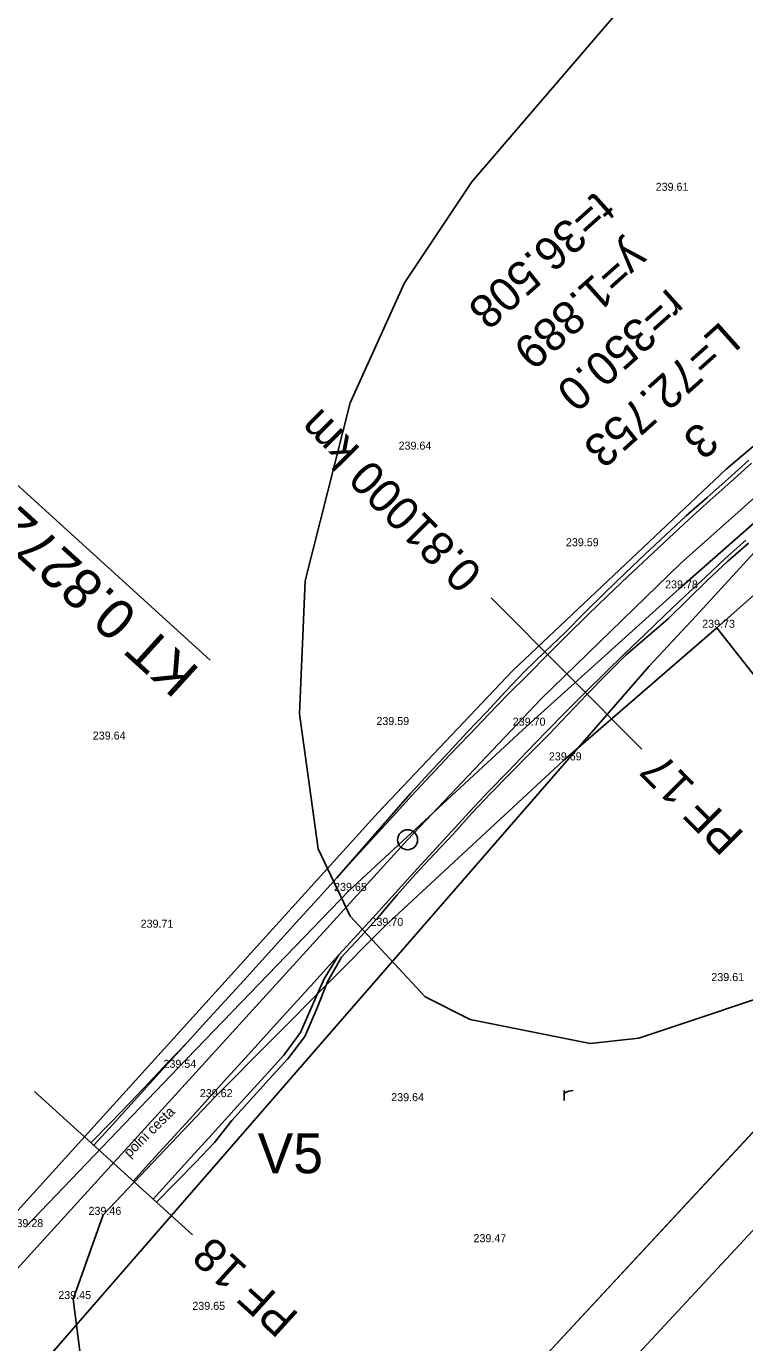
# Model space of a CAD drawing. Extents: x -555887 to -552101, y -1100251 to -1096546.
# Drawn here: x -555426.4 to -555372.6, y -1098751.9 to -1098653.3 of the extents above; entities that cross this region are included whole.
import ezdxf

# ---------------------------------------------------------------- set-up
doc = ezdxf.new("R2010")
doc.units = 0
for name, color, linetype in [('PARCELY_cesty', 7, 'Continuous'), ('POLYGONY_POPIS_CESTY', 7, 'Continuous'), ('POLYGONY_SITUACE_PF', 7, 'Continuous'), ('POLYGONY_SITUACE_PF_POPISY', 7, 'Continuous'), ('POLYGONY_SITUACE_PO', 7, 'Continuous'), ('ram_VC1', 7, 'Continuous'), ('vrstevnice', 7, 'Continuous'), ('Výškopis', 7, 'Continuous'), ('ZSST', 7, 'Continuous'), ('zájem', 7, 'Continuous')]:
    doc.layers.add(name, color=color, linetype=linetype)

msp = doc.modelspace()

# ---------------------------------------------------------------- linework, layer by layer
msp.add_line((-555412.608, -1098700.796), (-555428.216, -1098686.609))
at = {"layer": 'PARCELY_cesty'}
msp.add_lwpolyline([(-555432.8, -1098748.4), (-555400.008, -1098712.208), (-555389.921, -1098701.565), (-555373.936, -1098686.469), (-555357.132, -1098672.276), (-555340.17, -1098659.659), (-555299.833, -1098630.198), (-555259.851, -1098600.294), (-555132.603, -1098503.989), (-555074.98, -1098461.38), (-555070.799, -1098455.669), (-555054.379, -1098443.798), (-555047.89, -1098441.68), (-555024.771, -1098425.173), (-554988.252, -1098399.708), (-554740.35, -1098228.23), (-554737.92, -1098224.21)], dxfattribs=at)
at = {"layer": 'POLYGONY_SITUACE_PF'}
for p, q in [((-555385.902, -1098701.782), (-555391.549, -1098696.116)), ((-555380.254, -1098707.448), (-555385.902, -1098701.782)), ((-555419.844, -1098738.489), (-555425.763, -1098733.108)), ((-555413.924, -1098743.871), (-555419.844, -1098738.489))]:
    msp.add_line(p, q, dxfattribs=at)
at = {"layer": 'POLYGONY_SITUACE_PO'}
for p, q in [((-555366.511, -1098683.861), (-555377.362, -1098693.554)), ((-555372.241, -1098685.8), (-555373.797, -1098687.206)), ((-555372.04, -1098686.028), (-555373.604, -1098687.421)), ((-555372.04, -1098686.028), (-555373.604, -1098687.421)), ((-555373.797, -1098687.206), (-555375.371, -1098688.592)), ((-555373.604, -1098687.421), (-555375.162, -1098688.823)), ((-555373.604, -1098687.421), (-555375.162, -1098688.823)), ((-555375.371, -1098688.592), (-555376.94, -1098689.983)), ((-555375.162, -1098688.823), (-555376.715, -1098690.229)), ((-555375.162, -1098688.823), (-555376.715, -1098690.229)), ((-555376.94, -1098689.983), (-555378.479, -1098691.408)), ((-555376.715, -1098690.229), (-555378.249, -1098691.656)), ((-555376.715, -1098690.229), (-555378.249, -1098691.656)), ((-555378.479, -1098691.408), (-555380.005, -1098692.847)), ((-555378.249, -1098691.656), (-555379.783, -1098693.083)), ((-555378.249, -1098691.656), (-555379.783, -1098693.083)), ((-555372.476, -1098691.787), (-555374.011, -1098693.177)), ((-555372.476, -1098691.787), (-555374.011, -1098693.177)), ((-555372.261, -1098692.025), (-555373.826, -1098693.38)), ((-555380.005, -1098692.847), (-555381.526, -1098694.291)), ((-555379.783, -1098693.083), (-555381.304, -1098694.525)), ((-555379.783, -1098693.083), (-555381.304, -1098694.525)), ((-555374.011, -1098693.177), (-555375.528, -1098694.588)), ((-555374.011, -1098693.177), (-555375.528, -1098694.588)), ((-555377.362, -1098693.554), (-555387.8, -1098703.689)), ((-555373.826, -1098693.38), (-555375.341, -1098694.79)), ((-555381.526, -1098694.291), (-555383.043, -1098695.739)), ((-555381.304, -1098694.525), (-555382.821, -1098695.97)), ((-555381.304, -1098694.525), (-555382.821, -1098695.97)), ((-555375.528, -1098694.588), (-555377.045, -1098695.999)), ((-555375.528, -1098694.588), (-555377.045, -1098695.999)), ((-555375.341, -1098694.79), (-555376.82, -1098696.239)), ((-555383.043, -1098695.739), (-555384.521, -1098697.227)), ((-555382.821, -1098695.97), (-555384.328, -1098697.425)), ((-555382.821, -1098695.97), (-555384.328, -1098697.425)), ((-555377.045, -1098695.999), (-555378.548, -1098697.424)), ((-555377.045, -1098695.999), (-555378.548, -1098697.424)), ((-555376.82, -1098696.239), (-555378.298, -1098697.687)), ((-555384.521, -1098697.227), (-555385.997, -1098698.716)), ((-555384.328, -1098697.425), (-555385.821, -1098698.895)), ((-555384.328, -1098697.425), (-555385.821, -1098698.895)), ((-555378.548, -1098697.424), (-555380.048, -1098698.853)), ((-555378.548, -1098697.424), (-555380.048, -1098698.853)), ((-555378.298, -1098697.687), (-555379.864, -1098699.044)), ((-555385.997, -1098698.716), (-555387.523, -1098700.155)), ((-555385.821, -1098698.895), (-555387.314, -1098700.365)), ((-555385.821, -1098698.895), (-555387.314, -1098700.365)), ((-555380.048, -1098698.853), (-555381.538, -1098700.292)), ((-555380.048, -1098698.853), (-555381.538, -1098700.292)), ((-555379.864, -1098699.044), (-555381.432, -1098700.401)), ((-555387.523, -1098700.155), (-555389.032, -1098701.613)), ((-555387.314, -1098700.365), (-555388.789, -1098701.853)), ((-555387.314, -1098700.365), (-555388.789, -1098701.853)), ((-555381.538, -1098700.292), (-555383.014, -1098701.745)), ((-555381.538, -1098700.292), (-555383.014, -1098701.745)), ((-555381.432, -1098700.401), (-555382.905, -1098701.856)), ((-555389.032, -1098701.613), (-555390.476, -1098703.133)), ((-555388.789, -1098701.853), (-555390.264, -1098703.342)), ((-555388.789, -1098701.853), (-555390.264, -1098703.342)), ((-555383.014, -1098701.745), (-555384.49, -1098703.199)), ((-555383.014, -1098701.745), (-555384.49, -1098703.199)), ((-555382.905, -1098701.856), (-555384.357, -1098703.331)), ((-555387.8, -1098703.689), (-555397.809, -1098714.249)), ((-555390.476, -1098703.133), (-555391.895, -1098704.679)), ((-555390.264, -1098703.342), (-555391.724, -1098704.844)), ((-555390.264, -1098703.342), (-555391.724, -1098704.844)), ((-555384.49, -1098703.199), (-555385.948, -1098704.67)), ((-555384.49, -1098703.199), (-555385.948, -1098704.67)), ((-555384.357, -1098703.331), (-555385.784, -1098704.832)), ((-555391.895, -1098704.679), (-555393.344, -1098706.194)), ((-555391.724, -1098704.844), (-555393.174, -1098706.356)), ((-555391.724, -1098704.844), (-555393.174, -1098706.356)), ((-555385.948, -1098704.67), (-555387.406, -1098706.141)), ((-555385.948, -1098704.67), (-555387.406, -1098706.141)), ((-555385.784, -1098704.832), (-555387.209, -1098706.335)), ((-555393.344, -1098706.194), (-555394.779, -1098707.723)), ((-555393.174, -1098706.356), (-555394.622, -1098707.871)), ((-555393.174, -1098706.356), (-555394.622, -1098707.871)), ((-555387.406, -1098706.141), (-555388.85, -1098707.626)), ((-555387.406, -1098706.141), (-555388.85, -1098707.626)), ((-555387.209, -1098706.335), (-555388.665, -1098707.806)), ((-555394.779, -1098707.723), (-555396.203, -1098709.261)), ((-555394.622, -1098707.871), (-555396.058, -1098709.396)), ((-555394.622, -1098707.871), (-555396.058, -1098709.396)), ((-555388.85, -1098707.626), (-555390.284, -1098709.121)), ((-555388.85, -1098707.626), (-555390.284, -1098709.121)), ((-555388.665, -1098707.806), (-555390.115, -1098709.283)), ((-555396.203, -1098709.261), (-555397.615, -1098710.811)), ((-555396.058, -1098709.396), (-555397.482, -1098710.933)), ((-555396.058, -1098709.396), (-555397.482, -1098710.933)), ((-555390.284, -1098709.121), (-555391.715, -1098710.619)), ((-555390.284, -1098709.121), (-555391.715, -1098710.619)), ((-555390.115, -1098709.283), (-555391.571, -1098710.755)), ((-555397.615, -1098710.811), (-555398.991, -1098712.393)), ((-555397.482, -1098710.933), (-555398.899, -1098712.477)), ((-555397.482, -1098710.933), (-555398.899, -1098712.477)), ((-555391.715, -1098710.619), (-555393.135, -1098712.127)), ((-555391.715, -1098710.619), (-555393.135, -1098712.127)), ((-555391.571, -1098710.755), (-555392.986, -1098712.266)), ((-555398.991, -1098712.393), (-555400.365, -1098713.964)), ((-555398.899, -1098712.477), (-555400.303, -1098714.02)), ((-555398.899, -1098712.477), (-555400.303, -1098714.02)), ((-555393.135, -1098712.127), (-555394.543, -1098713.646)), ((-555393.135, -1098712.127), (-555394.543, -1098713.646)), ((-555392.986, -1098712.266), (-555394.376, -1098713.8)), ((-555394.543, -1098713.646), (-555395.944, -1098715.172)), ((-555394.543, -1098713.646), (-555395.944, -1098715.172)), ((-555394.376, -1098713.8), (-555395.786, -1098715.316)), ((-555397.809, -1098714.249), (-555428.322, -1098747.816)), ((-555400.365, -1098713.964), (-555401.746, -1098715.524)), ((-555400.303, -1098714.02), (-555401.705, -1098715.562)), ((-555400.303, -1098714.02), (-555401.705, -1098715.562)), ((-555401.746, -1098715.524), (-555403.115, -1098717.096)), ((-555401.705, -1098715.562), (-555403.106, -1098717.103)), ((-555401.705, -1098715.562), (-555403.106, -1098717.103)), ((-555395.944, -1098715.172), (-555397.344, -1098716.711)), ((-555395.944, -1098715.172), (-555397.344, -1098716.711)), ((-555395.786, -1098715.316), (-555397.209, -1098716.834)), ((-555397.344, -1098716.711), (-555398.745, -1098718.252)), ((-555397.344, -1098716.711), (-555398.745, -1098718.252)), ((-555397.209, -1098716.834), (-555398.602, -1098718.382)), ((-555403.115, -1098717.096), (-555404.507, -1098718.645)), ((-555403.106, -1098717.103), (-555404.507, -1098718.645)), ((-555403.106, -1098717.103), (-555404.507, -1098718.645)), ((-555404.507, -1098718.645), (-555405.909, -1098720.187)), ((-555404.507, -1098718.645), (-555405.909, -1098720.187)), ((-555404.507, -1098718.645), (-555405.909, -1098720.187)), ((-555404.507, -1098718.645), (-555404.507, -1098718.645)), ((-555398.745, -1098718.252), (-555400.146, -1098719.794)), ((-555398.745, -1098718.252), (-555400.146, -1098719.794)), ((-555398.602, -1098718.382), (-555399.937, -1098719.985)), ((-555400.146, -1098719.794), (-555401.548, -1098721.336)), ((-555400.146, -1098719.794), (-555401.548, -1098721.336)), ((-555405.909, -1098720.187), (-555407.31, -1098721.728)), ((-555405.909, -1098720.187), (-555407.31, -1098721.728)), ((-555405.909, -1098720.187), (-555407.31, -1098721.728)), ((-555399.937, -1098719.985), (-555401.343, -1098721.522)), ((-555407.31, -1098721.728), (-555408.711, -1098723.27)), ((-555407.31, -1098721.728), (-555408.711, -1098723.27)), ((-555407.31, -1098721.728), (-555408.711, -1098723.27)), ((-555401.548, -1098721.336), (-555402.949, -1098722.877)), ((-555401.548, -1098721.336), (-555402.949, -1098722.877)), ((-555401.343, -1098721.522), (-555402.755, -1098723.053)), ((-555408.711, -1098723.27), (-555410.113, -1098724.811)), ((-555408.711, -1098723.27), (-555410.113, -1098724.811)), ((-555408.711, -1098723.27), (-555410.113, -1098724.811)), ((-555402.949, -1098722.877), (-555404.35, -1098724.419)), ((-555402.949, -1098722.877), (-555404.062, -1098724.68)), ((-555402.755, -1098723.053), (-555403.815, -1098724.905)), ((-555404.35, -1098724.419), (-555405.752, -1098725.96)), ((-555404.062, -1098724.68), (-555404.95, -1098726.689)), ((-555410.113, -1098724.811), (-555411.514, -1098726.353)), ((-555410.113, -1098724.811), (-555411.514, -1098726.353)), ((-555410.113, -1098724.811), (-555411.514, -1098726.353)), ((-555403.815, -1098724.905), (-555404.636, -1098726.974)), ((-555411.514, -1098726.353), (-555412.915, -1098727.895)), ((-555411.514, -1098726.353), (-555412.915, -1098727.895)), ((-555411.514, -1098726.353), (-555412.915, -1098727.895)), ((-555405.752, -1098725.96), (-555407.153, -1098727.502)), ((-555404.95, -1098726.689), (-555405.837, -1098728.698)), ((-555407.153, -1098727.502), (-555408.554, -1098729.044)), ((-555404.636, -1098726.974), (-555405.521, -1098728.985)), ((-555412.915, -1098727.895), (-555414.317, -1098729.436)), ((-555412.915, -1098727.895), (-555414.317, -1098729.436)), ((-555412.915, -1098727.895), (-555414.317, -1098729.436)), ((-555405.837, -1098728.698), (-555407.074, -1098730.389)), ((-555414.317, -1098729.436), (-555415.767, -1098730.933)), ((-555414.317, -1098729.436), (-555415.718, -1098730.978)), ((-555414.317, -1098729.436), (-555415.718, -1098730.978)), ((-555414.317, -1098729.436), (-555414.317, -1098729.436)), ((-555408.554, -1098729.044), (-555409.956, -1098730.585)), ((-555405.521, -1098728.985), (-555406.772, -1098730.664)), ((-555409.956, -1098730.585), (-555411.357, -1098732.127)), ((-555407.074, -1098730.389), (-555408.476, -1098731.93)), ((-555406.772, -1098730.664), (-555408.176, -1098732.203)), ((-555415.767, -1098730.933), (-555417.189, -1098732.456)), ((-555415.718, -1098730.978), (-555417.12, -1098732.519)), ((-555415.718, -1098730.978), (-555417.12, -1098732.519)), ((-555417.189, -1098732.456), (-555418.617, -1098733.974)), ((-555417.12, -1098732.519), (-555418.521, -1098734.061)), ((-555417.12, -1098732.519), (-555418.521, -1098734.061)), ((-555411.357, -1098732.127), (-555412.758, -1098733.668)), ((-555408.476, -1098731.93), (-555409.877, -1098733.472)), ((-555408.176, -1098732.203), (-555409.573, -1098733.748)), ((-555409.877, -1098733.472), (-555411.278, -1098735.014)), ((-555418.617, -1098733.974), (-555420.064, -1098735.473)), ((-555418.521, -1098734.061), (-555419.922, -1098735.603)), ((-555418.521, -1098734.061), (-555419.922, -1098735.603)), ((-555412.758, -1098733.668), (-555414.16, -1098735.21)), ((-555409.573, -1098733.748), (-555410.976, -1098735.289)), ((-555420.064, -1098735.473), (-555421.53, -1098736.956)), ((-555419.922, -1098735.603), (-555421.324, -1098737.144)), ((-555419.922, -1098735.603), (-555421.324, -1098737.144)), ((-555414.16, -1098735.21), (-555415.561, -1098736.752)), ((-555411.278, -1098735.014), (-555412.68, -1098736.555)), ((-555410.976, -1098735.289), (-555412.271, -1098736.927)), ((-555412.68, -1098736.555), (-555414.081, -1098738.097)), ((-555415.561, -1098736.752), (-555416.962, -1098738.293)), ((-555412.271, -1098736.927), (-555413.705, -1098738.438)), ((-555416.962, -1098738.293), (-555418.364, -1098739.835)), ((-555414.081, -1098738.097), (-555415.482, -1098739.638)), ((-555413.705, -1098738.438), (-555415.165, -1098739.927)), ((-555415.482, -1098739.638), (-555416.884, -1098741.18)), ((-555415.165, -1098739.927), (-555416.627, -1098741.413))]:
    msp.add_line(p, q, dxfattribs=at)
msp.add_circle((-555397.809, -1098714.249), 0.75, dxfattribs=at)
at = {"layer": 'ram_VC1'}
for points in [[(-554540.883, -1097849.107), (-554911.618, -1097504.634), (-555880.616, -1098547.506), (-555509.881, -1098891.979)], [(-554547.95, -1097849.366), (-554911.358, -1097511.7), (-555873.55, -1098547.246), (-555510.141, -1098884.912)]]:
    msp.add_lwpolyline(points, close=True, dxfattribs=at)
for points in [[(-554540.883, -1097849.107), (-554911.618, -1097504.634), (-555880.616, -1098547.506), (-555509.881, -1098891.979), (-554540.883, -1097849.107)], [(-555510.141, -1098884.912), (-555873.55, -1098547.246), (-554911.358, -1097511.7), (-554547.95, -1097849.366), (-555510.141, -1098884.912)]]:
    msp.add_lwpolyline(points, dxfattribs=at)
at = {"layer": 'vrstevnice'}
msp.add_lwpolyline([(-555306.349, -1098681.23), (-555357.179, -1098717.88), (-555367.859, -1098724.9), (-555380.489, -1098729.11), (-555384.139, -1098729.53), (-555393.129, -1098727.71), (-555396.499, -1098726.02), (-555402.119, -1098719.98), (-555404.499, -1098714.93), (-555405.909, -1098704.82), (-555405.489, -1098694.85), (-555402.119, -1098681.51), (-555398.049, -1098672.52), (-555392.989, -1098664.94), (-555377.829, -1098647.25), (-555362.519, -1098631.24), (-555353.669, -1098619.73), (-555346.649, -1098606.59), (-555345.389, -1098601.19)], dxfattribs=at)
at = {"layer": 'ZSST'}
msp.add_line((-555374.63, -1098698.36), (-555361.85, -1098714.7), dxfattribs=at)
for points in [[(-555047.93, -1098442.03), (-555072.12, -1098458.86), (-555088.34, -1098470.57), (-555126.84, -1098498.87), (-555144.37, -1098512.2), (-555194.54, -1098551.36), (-555231.55, -1098580.01), (-555250.25, -1098594.37), (-555270.85, -1098609.63), (-555289.58, -1098622.71), (-555305.43, -1098634.04), (-555318.12, -1098644.14), (-555342.33, -1098664.59), (-555361.73, -1098681.61), (-555377.43, -1098695.41), (-555388.84, -1098705.7), (-555402.21, -1098718.08), (-555414.99, -1098731.34), (-555426.44, -1098743.28)], [(-555374.63, -1098698.36), (-555358.9, -1098684.46), (-555339.75, -1098668.11), (-555314.71, -1098647.33), (-555303.03, -1098637.47), (-555287.5, -1098626.12)], [(-555416.24, -1098769.34), (-555421.95, -1098755.88), (-555422.87, -1098748.67), (-555420.62, -1098742.36), (-555412.26, -1098733.54), (-555399.5, -1098720.7), (-555386.13, -1098708.3), (-555374.63, -1098698.36)], [(-555386.084, -1098733.783), (-555386.084, -1098733.051)], [(-555386.084, -1098733.287), (-555385.982, -1098733.192), (-555385.879, -1098733.129), (-555385.722, -1098733.082), (-555385.572, -1098733.059), (-555385.415, -1098733.051)]]:
    msp.add_lwpolyline(points, dxfattribs=at)
at = {"layer": 'zájem'}
for points in [[(-555456.8, -1098789.9), (-555379.7, -1098701.24), (-555376.22, -1098697.48), (-555369.9, -1098690.59), (-555369.08, -1098690.01), (-555302.67, -1098640.32), (-555268.63, -1098614.85), (-555156.39, -1098530.87), (-555094.92, -1098484.89), (-555072.69, -1098467.65), (-555057.79, -1098455.7), (-554947.91, -1098379.76)], [(-554947.91, -1098379.76), (-555057.79, -1098455.7), (-555072.69, -1098467.65), (-555094.92, -1098484.89), (-555156.39, -1098530.87), (-555268.63, -1098614.85), (-555302.67, -1098640.32), (-555369.08, -1098690.01), (-555369.9, -1098690.59), (-555376.22, -1098697.48), (-555379.7, -1098701.24), (-555456.8, -1098789.9)]]:
    msp.add_lwpolyline(points, dxfattribs=at)

# ---------------------------------------------------------------- texts
for s, height, rotation, p in [('t=36.508', 2.5, 221.77345, (-555383.665, -1098665.561)), ('y=1.889', 2.5, 221.77345, (-555381.112, -1098669.314)), ('r=350.0', 2.5, 221.77345, (-555378.3, -1098672.837)), ('L=72.753', 2.5, 221.77345, (-555374.327, -1098675.321)), ('3', 2.5, 221.77345, (-555375.947, -1098682.803)), ('KT 0.82724', 3, 137.72832, (-555413.281, -1098701.536))]:
    msp.add_text(s, height=height, rotation=rotation).set_placement(p)
at = {"layer": 'POLYGONY_POPIS_CESTY'}
msp.add_text('V5', height=3, rotation=359.89336, dxfattribs=at).set_placement((-555409.053, -1098739.24))
at = {"layer": 'POLYGONY_SITUACE_PF_POPISY'}
for s, rotation, p in [('0.81000 km', 134.90586, (-555392.079, -1098694.168)), ('PF 17', 134.90586, (-555372.487, -1098713.825)), ('PF 18', 137.72832, (-555405.852, -1098749.857))]:
    msp.add_text(s, height=2.5, rotation=rotation, dxfattribs=at).set_placement(p)
at = {"layer": 'Výškopis'}
for s, p in [('239.61', (-555379.222, -1098665.61)), ('239.64', (-555398.484, -1098685.01)), ('239.59', (-555385.948, -1098692.25)), ('239.78', (-555378.518, -1098695.41)), ('239.73', (-555375.738, -1098698.36)), ('239.59', (-555400.148, -1098705.65)), ('239.70', (-555389.93, -1098705.7)), ('239.64', (-555421.394, -1098706.74)), ('239.69', (-555387.224, -1098708.3)), ('239.65', (-555403.318, -1098718.08)), ('239.71', (-555417.81, -1098720.84)), ('239.70', (-555400.59, -1098720.7)), ('239.61', (-555375.052, -1098724.84)), ('239.54', (-555416.098, -1098731.34)), ('239.62', (-555413.376, -1098733.54)), ('239.64', (-555399.034, -1098733.84)), ('239.46', (-555421.714, -1098742.36)), ('239.28', (-555427.562, -1098743.28)), ('239.47', (-555392.873, -1098744.41)), ('239.45', (-555423.978, -1098748.67)), ('239.65', (-555413.938, -1098749.48))]:
    msp.add_text(s, height=0.6, dxfattribs=at).set_placement(p)
at = {"layer": 'ZSST'}
msp.add_text('polní cesta', height=0.75, rotation=44.63341, dxfattribs=at).set_placement((-555418.636, -1098738.108))

doc.saveas('drawing.dxf')
